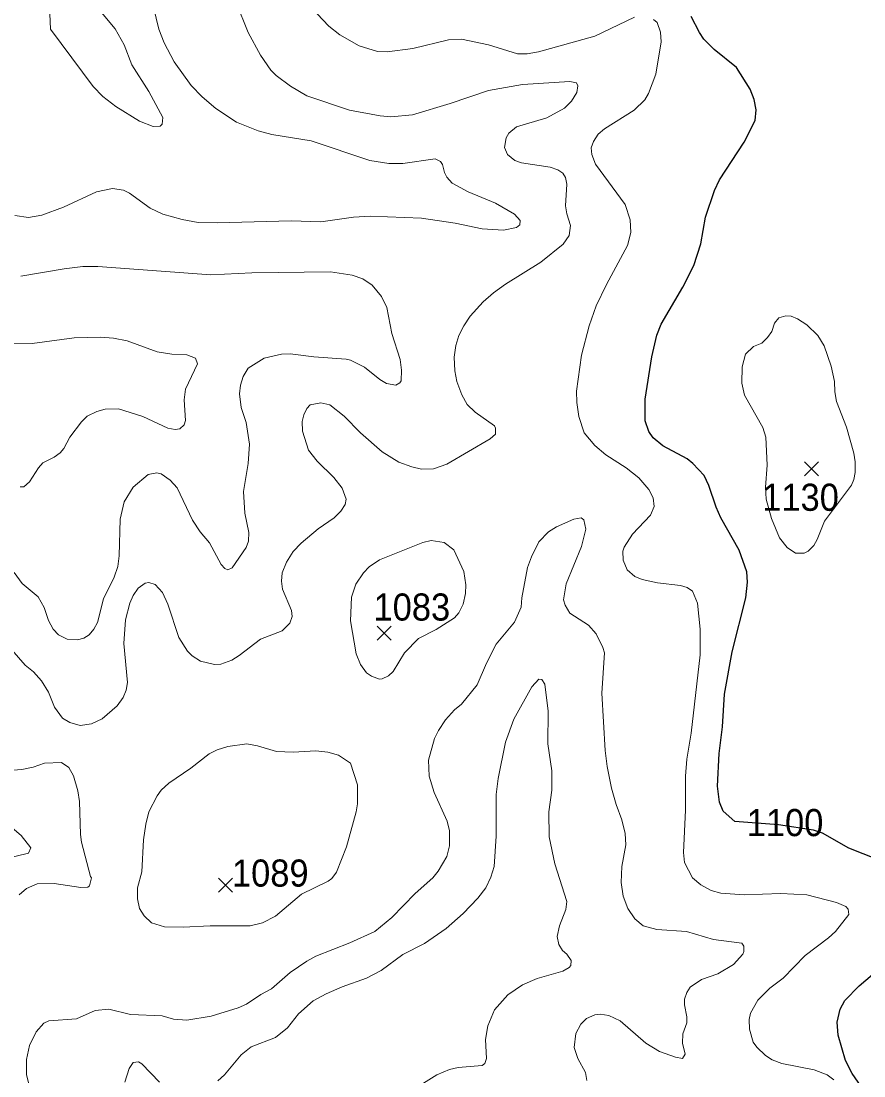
# Model space of a CAD drawing. Extents: x 265 to 291.4, y 7731.5 to 7759.6.
# Drawn here: x 278.229 to 280.715, y 7740.103 to 7743.215 of the extents above; entities that cross this region are included whole.
import ezdxf
from ezdxf.enums import TextEntityAlignment as Align

# ---------------------------------------------------------------- set-up
doc = ezdxf.new("R2010")
doc.units = 0
doc.header["$LTSCALE"] = 0.032
for name, color, linetype, lineweight in [('1', 7, 'Continuous', 25), ('2', 7, 'Continuous', 13), ('21', 7, 'Continuous', 25), ('61', 7, 'Continuous', 13)]:
    doc.layers.add(name, color=color, linetype=linetype, lineweight=lineweight)

msp = doc.modelspace()

# ---------------------------------------------------------------- linework, layer by layer
at = {"layer": '1'}
for points in [[(280.0695, 7742.0994), (280.0894, 7742.225), (280.1037, 7742.2887), (280.1165, 7742.3205), (280.1809, 7742.4303), (280.2127, 7742.4939), (280.2334, 7742.5576), (280.2477, 7742.6371), (280.274, 7742.7151), (280.2883, 7742.7469), (280.3615, 7742.8583), (280.3941, 7742.9219), (280.3973, 7742.9537), (280.3909, 7742.9839), (280.379, 7743.0142), (280.3384, 7743.0778), (280.2732, 7743.1311), (280.243, 7743.1613), (280.2294, 7743.1812), (280.2048, 7743.2289)], [(280.2103, 7741.91), (280.1929, 7741.9235), (280.1213, 7741.9617), (280.0926, 7741.9856), (280.0807, 7742.0039), (280.0695, 7742.0357), (280.0695, 7742.0994)], [(280.7974, 7740.7247), (280.6701, 7740.7756), (280.593, 7740.8194), (280.5655, 7740.8287), (280.4625, 7740.844), (280.3344, 7740.8544), (280.2994, 7740.8846), (280.2891, 7740.9109), (280.2827, 7740.9586), (280.2875, 7741.0541), (280.2978, 7741.1336), (280.3034, 7741.2291), (280.3257, 7741.3548), (280.3663, 7741.5139), (280.3718, 7741.56), (280.3694, 7741.5903), (280.3464, 7741.6539), (280.2931, 7741.7493), (280.2787, 7741.7812), (280.2573, 7741.8448), (280.2437, 7741.875), (280.2103, 7741.91)], [(280.7258, 7740.0438), (280.6797, 7740.1107), (280.6606, 7740.1488), (280.6383, 7740.2236), (280.6359, 7740.2618), (280.6447, 7740.3), (280.6582, 7740.3254), (280.7003, 7740.3692), (280.8117, 7740.4638)]]:
    msp.add_lwpolyline(points, dxfattribs=at)
at = {"layer": '2'}
for points in [[(278.5939, 7743.3626), (278.6345, 7743.1908), (278.6504, 7743.151), (278.6806, 7743.0945), (278.7307, 7743.0253), (278.7626, 7742.9919), (278.8031, 7742.9569), (278.8644, 7742.9171), (278.928, 7742.8909), (278.9678, 7742.8805), (279.084, 7742.8614), (279.2574, 7742.8042), (279.3131, 7742.7954), (279.3544, 7742.7946), (279.4499, 7742.8089), (279.4658, 7742.801), (279.4713, 7742.7922), (279.4777, 7742.7684), (279.4849, 7742.7548), (279.5, 7742.7373), (279.5469, 7742.7111), (279.6281, 7742.6777), (279.6845, 7742.6451), (279.7012, 7742.6268), (279.6996, 7742.614), (279.6901, 7742.6061), (279.6519, 7742.5981), (279.5883, 7742.6021), (279.5087, 7742.6188), (279.4101, 7742.6339), (279.259, 7742.6395), (279.2096, 7742.6363), (279.1126, 7742.6228), (279.0251, 7742.626), (278.8071, 7742.6196), (278.7514, 7742.6212), (278.7037, 7742.6299)], [(278.3131, 7743.2369), (278.3155, 7743.1915), (278.4412, 7743.0221), (278.4698, 7742.9927), (278.508, 7742.9632), (278.578, 7742.9195), (278.6178, 7742.9044), (278.6385, 7742.9052), (278.6448, 7742.9107), (278.6464, 7742.9306), (278.6051, 7743.0078), (278.5549, 7743.0858), (278.5327, 7743.1446), (278.5064, 7743.1924), (278.4515, 7743.2584)], [(278.9654, 7743.0706), (278.9344, 7743.1144), (278.8986, 7743.1812), (278.862, 7743.2719)], [(279.1022, 7743.2361), (279.1364, 7743.2003), (279.1691, 7743.174), (279.2255, 7743.1422), (279.2796, 7743.1255), (279.3083, 7743.1239), (279.3846, 7743.1343), (279.4896, 7743.1597), (279.5278, 7743.1621), (279.6074, 7743.1454), (279.6933, 7743.1184), (279.7219, 7743.1184), (279.7553, 7743.1247), (279.9208, 7743.1701), (280.0377, 7743.2265)], [(280.0942, 7743.2202), (280.1053, 7743.2106), (280.1149, 7743.1828), (280.1165, 7743.1542), (280.1014, 7743.0587), (280.0791, 7743.0014), (280.068, 7742.9823), (280.0369, 7742.9521), (279.9494, 7742.8972), (279.9311, 7742.8813), (279.9168, 7742.8598), (279.9104, 7742.8408), (279.912, 7742.8217), (279.9232, 7742.793), (280.0107, 7742.6737), (280.025, 7742.6292), (280.0274, 7742.591), (280.017, 7742.5528), (279.955, 7742.4382), (279.9248, 7742.3746), (279.9041, 7742.3157), (279.8818, 7742.2298), (279.8667, 7742.1232), (279.8675, 7742.0898), (279.8739, 7742.0485), (279.8898, 7742.0007), (279.9208, 7741.9633), (279.9534, 7741.9355), (280.0131, 7741.8973), (280.0505, 7741.8679), (280.0799, 7741.8329)], [(279.3194, 7742.933), (279.2876, 7742.9354), (279.1969, 7742.9521), (279.0712, 7742.9943), (279.0235, 7743.0229), (278.9813, 7743.0547), (278.9654, 7743.0706)], [(278.5947, 7741.5568), (278.6056, 7741.5588), (278.6241, 7741.5528), (278.6456, 7741.529), (278.6615, 7741.4948), (278.6941, 7741.3962), (278.7196, 7741.3564), (278.7331, 7741.3429), (278.7578, 7741.3269), (278.7992, 7741.3166), (278.8183, 7741.3182), (278.8501, 7741.3301), (278.8724, 7741.3436), (278.9344, 7741.3922), (278.9988, 7741.416), (279.0211, 7741.4391), (279.0283, 7741.4582), (279.0267, 7741.4765), (278.9996, 7741.5393), (278.9964, 7741.5632), (278.9988, 7741.5871), (279.0115, 7741.6189), (279.0314, 7741.6507), (279.0545, 7741.6746), (279.1046, 7741.7175), (279.1524, 7741.7501), (279.1714, 7741.7692), (279.1842, 7741.7891), (279.1874, 7741.805), (279.1754, 7741.8369), (279.1508, 7741.8687), (279.1022, 7741.9172), (279.0768, 7741.949), (279.0585, 7742.0055), (279.0577, 7742.0341), (279.0625, 7742.0532), (279.072, 7742.0723), (279.0816, 7742.0835), (279.1126, 7742.089), (279.1396, 7742.0826), (279.1818, 7742.05), (279.2295, 7742.0007), (279.294, 7741.9442), (279.3433, 7741.914), (279.3815, 7741.8997), (279.4101, 7741.8933), (279.4451, 7741.8941), (279.4849, 7741.9076), (279.6121, 7741.9824), (279.6281, 7741.9967), (279.6281, 7742.0142), (279.6249, 7742.0206), (279.5676, 7742.0612), (279.5445, 7742.0842), (279.5286, 7742.1121), (279.5143, 7742.1519), (279.5079, 7742.1837), (279.5063, 7742.2235), (279.5111, 7742.2585), (279.5199, 7742.2871), (279.5342, 7742.3157), (279.5533, 7742.3444), (279.5915, 7742.3865), (279.6217, 7742.4136), (279.6575, 7742.439), (279.7617, 7742.5034), (279.8277, 7742.5568), (279.8452, 7742.583), (279.8492, 7742.6117), (279.8381, 7742.6467), (279.8341, 7742.6705), (279.8389, 7742.7342), (279.8349, 7742.754), (279.8269, 7742.766), (279.8118, 7742.7763), (279.7888, 7742.7843), (279.7044, 7742.797), (279.6853, 7742.8042), (279.6631, 7742.8217), (279.6543, 7742.8423), (279.6591, 7742.871), (279.667, 7742.8845), (279.6901, 7742.9028), (279.7792, 7742.9298), (279.8317, 7742.9585), (279.8524, 7742.9792), (279.8675, 7743.0046), (279.8707, 7743.0245), (279.8667, 7743.0325), (279.8476, 7743.0372), (279.7076, 7743.0277), (279.6074, 7743.0102), (279.4944, 7742.972), (279.3831, 7742.9386), (279.3194, 7742.933)], [(278.7037, 7742.6299), (278.6464, 7742.6458), (278.6098, 7742.6633), (278.5486, 7742.7079), (278.5303, 7742.7158), (278.4985, 7742.7214), (278.4507, 7742.7111)], [(278.4507, 7742.7111), (278.3537, 7742.6665), (278.2901, 7742.6427), (278.2503, 7742.6355), (278.2105, 7742.6411)], [(278.228, 7742.4629), (278.3553, 7742.4844), (278.411, 7742.4907), (278.4555, 7742.4907), (278.788, 7742.4669), (278.9089, 7742.4724), (279.1412, 7742.4756), (279.2049, 7742.4653), (279.2367, 7742.4549), (279.2645, 7742.4358), (279.2916, 7742.4024), (279.3075, 7742.3698), (279.3226, 7742.2935), (279.3472, 7742.2171), (279.3512, 7742.1853), (279.3496, 7742.1542), (279.3457, 7742.1479), (279.3345, 7742.1415), (279.3067, 7742.1463), (279.2868, 7742.1574), (279.2415, 7742.194), (279.2001, 7742.2147), (279.1874, 7742.2179), (279.0919, 7742.2242), (279.0219, 7742.233), (278.9964, 7742.2322), (278.9455, 7742.2203), (278.8986, 7742.1908), (278.8835, 7742.167), (278.8755, 7742.1407), (278.8731, 7742.1153), (278.8779, 7742.0755)], [(278.2256, 7741.8416), (278.2367, 7741.8416), (278.2535, 7741.8559), (278.2805, 7741.8973), (278.2932, 7741.9116), (278.3267, 7741.9283), (278.3442, 7741.9418), (278.3545, 7741.9546), (278.3728, 7741.988), (278.407, 7742.0333), (278.4237, 7742.0492), (278.4523, 7742.0636), (278.4762, 7742.0707), (278.516, 7742.0715), (278.5876, 7742.0484), (278.6615, 7742.0142), (278.683, 7742.0102), (278.6973, 7742.0118), (278.7093, 7742.0238), (278.714, 7742.0373), (278.7101, 7742.0978), (278.714, 7742.1296), (278.749, 7742.2035), (278.7435, 7742.2211), (278.718, 7742.2306), (278.6735, 7742.2322), (278.6305, 7742.2394), (278.5414, 7742.272), (278.5017, 7742.2799), (278.4619, 7742.2823), (278.3855, 7742.2807), (278.2614, 7742.264), (278.2057, 7742.2632)], [(278.8779, 7742.0755), (278.8922, 7742.031), (278.9026, 7741.9673), (278.8986, 7741.91), (278.8843, 7741.8273), (278.889, 7741.7637), (278.9002, 7741.7064)], [(278.9002, 7741.7064), (278.8994, 7741.6809), (278.893, 7741.6618), (278.8509, 7741.6022), (278.8389, 7741.5966), (278.8294, 7741.5998), (278.819, 7741.6125), (278.7848, 7741.6762), (278.757, 7741.7088), (278.7347, 7741.743), (278.6886, 7741.8384), (278.6687, 7741.8607), (278.6417, 7741.879), (278.6289, 7741.8822), (278.6035, 7741.8774), (278.5589, 7741.84), (278.5327, 7741.7971), (278.5207, 7741.7462), (278.5176, 7741.638), (278.5136, 7741.6062), (278.5032, 7741.5743), (278.4722, 7741.5107), (278.4539, 7741.4407), (278.4436, 7741.4216), (278.4293, 7741.4041), (278.4142, 7741.3945), (278.3951, 7741.3898), (278.3648, 7741.3914), (278.3394, 7741.4041), (278.3235, 7741.4216), (278.3099, 7741.4471), (278.2972, 7741.4852), (278.2789, 7741.5171), (278.232, 7741.556), (278.2081, 7741.5887)], [(280.0799, 7741.8329), (280.0926, 7741.8082), (280.0958, 7741.7835), (280.0855, 7741.7573), (280.0322, 7741.7016), (280.0075, 7741.6634), (280.0035, 7741.6515)], [(280.0123, 7740.7852), (280.0107, 7740.8186), (280.0011, 7740.8584), (279.9836, 7740.9045), (279.9701, 7740.9523), (279.9574, 7741.0159), (279.9518, 7741.0636), (279.9415, 7741.2323), (279.9494, 7741.3516), (279.9446, 7741.3675), (279.9248, 7741.4073), (279.9025, 7741.4327), (279.8476, 7741.4685), (279.8333, 7741.4916), (279.8285, 7741.5075), (279.8365, 7741.5553), (279.8818, 7741.665), (279.8945, 7741.7159), (279.889, 7741.7438), (279.881, 7741.7493), (279.8587, 7741.7461), (279.8078, 7741.7231), (279.784, 7741.708), (279.7561, 7741.6785), (279.7338, 7741.6348), (279.7227, 7741.603), (279.7052, 7741.5139), (279.7036, 7741.486), (279.6845, 7741.4423), (279.6304, 7741.3771), (279.6018, 7741.3214), (279.574, 7741.2569), (279.5278, 7741.2005), (279.5071, 7741.183), (279.4809, 7741.1535), (279.4594, 7741.1225), (279.4483, 7741.0986), (279.43, 7741.035), (279.4324, 7740.9873), (279.4467, 7740.9395), (279.4857, 7740.8552), (279.492, 7740.8266), (279.492, 7740.782), (279.4841, 7740.7502), (279.4586, 7740.7073), (279.4435, 7740.6882), (279.391, 7740.642), (279.3226, 7740.5704), (279.2725, 7740.5299), (279.1985, 7740.4956), (279.0983, 7740.4567), (279.0712, 7740.4424), (279.0227, 7740.4089), (278.967, 7740.3604), (278.936, 7740.3437), (278.8938, 7740.3151), (278.8692, 7740.3039), (278.7896, 7740.2801), (278.718, 7740.2681), (278.6783, 7740.2705), (278.6448, 7740.2809), (278.551, 7740.2841), (278.4873, 7740.3), (278.4476, 7740.296), (278.3919, 7740.2721), (278.3107, 7740.2658), (278.2956, 7740.2594), (278.2733, 7740.2339), (278.2534, 7740.1934), (278.2447, 7740.152), (278.2447, 7740.1075), (278.2606, 7740.0438)], [(280.0035, 7741.6515), (280.0043, 7741.6253), (280.0162, 7741.5966), (280.0393, 7741.5767), (280.0608, 7741.568), (280.1054, 7741.5584), (280.1738, 7741.5505), (280.1929, 7741.5441), (280.2088, 7741.5338), (280.2239, 7741.498), (280.2318, 7741.4216), (280.2318, 7741.3452), (280.2048, 7741.1146), (280.192, 7741.0382), (280.1881, 7740.9873), (280.1881, 7740.887), (280.1825, 7740.7629), (280.1857, 7740.7327), (280.2087, 7740.6882), (280.2334, 7740.6667), (280.2645, 7740.6508), (280.2931, 7740.6428), (280.3615, 7740.6372), (280.4697, 7740.642), (280.5461, 7740.6373), (280.6336, 7740.615), (280.6614, 7740.6031), (280.6685, 7740.5951), (280.6701, 7740.5792), (280.6312, 7740.5299), (280.6105, 7740.5108), (280.5413, 7740.4591), (280.4768, 7740.3914), (280.4371, 7740.362), (280.4013, 7740.327), (280.3798, 7740.2888), (280.3766, 7740.2697), (280.3774, 7740.2411), (280.3877, 7740.2029), (280.3989, 7740.1878), (280.4243, 7740.1639), (280.4442, 7740.1512), (280.4729, 7740.1401), (280.5683, 7740.1218), (280.6065, 7740.1067), (280.6256, 7740.0915)], [(278.189, 7741.3755), (278.2407, 7741.315), (278.2654, 7741.2951), (278.2884, 7741.2689), (278.3091, 7741.2355), (278.3274, 7741.1909), (278.3513, 7741.1591), (278.372, 7741.1456), (278.403, 7741.1368), (278.4364, 7741.1416), (278.4682, 7741.1567), (278.512, 7741.1949), (278.5295, 7741.2196), (278.539, 7741.2418), (278.5422, 7741.2641), (278.5319, 7741.3787), (278.5366, 7741.4487), (278.5494, 7741.498), (278.5589, 7741.5202), (278.574, 7741.5425), (278.5947, 7741.5568)], [(278.8087, 7740.0892), (278.8286, 7740.1067), (278.8779, 7740.1655), (278.9074, 7740.1894), (278.9789, 7740.2164), (279.0147, 7740.2451), (279.0466, 7740.2864), (279.0903, 7740.3246), (279.1285, 7740.3453), (279.1762, 7740.366), (279.2478, 7740.3914), (279.2908, 7740.4145), (279.3544, 7740.4614), (279.4181, 7740.4941), (279.4825, 7740.5386), (279.5326, 7740.5824), (279.5756, 7740.6277), (279.5994, 7740.6579), (279.6145, 7740.6898), (279.6241, 7740.7216), (279.6304, 7740.8107), (279.6304, 7740.9332), (279.636, 7740.9809), (279.6575, 7741.0875), (279.6821, 7741.1559), (279.7354, 7741.2514), (279.7561, 7741.2736)], [(279.7561, 7741.2736), (279.7649, 7741.2728), (279.7736, 7741.2593), (279.7832, 7741.1798), (279.7824, 7741.0827), (279.7943, 7741.0032), (279.7943, 7740.9459)], [(278.2232, 7740.6373), (278.2447, 7740.6563), (278.2757, 7740.6699), (278.3267, 7740.6715), (278.4046, 7740.6595), (278.4253, 7740.6603), (278.4309, 7740.6643), (278.4364, 7740.6874), (278.4332, 7740.6913), (278.407, 7740.7932), (278.4038, 7740.8154), (278.4006, 7740.9125), (278.3958, 7740.9443), (278.3831, 7740.9889), (278.3696, 7741.0135), (278.3481, 7741.0278), (278.298, 7741.0262), (278.2646, 7741.0143), (278.2312, 7741.0071), (278.1373, 7741)], [(279.7943, 7740.9459), (279.7856, 7740.8823), (279.7864, 7740.8091), (279.8031, 7740.7295), (279.8389, 7740.6182), (279.8357, 7740.5943), (279.8166, 7740.5466), (279.8102, 7740.5148), (279.815, 7740.4909), (279.8253, 7740.4734), (279.8381, 7740.463), (279.8508, 7740.4439), (279.85, 7740.4296), (279.8452, 7740.4233), (279.8269, 7740.4129), (279.7506, 7740.3907), (279.7076, 7740.3724), (279.6639, 7740.3429), (279.6249, 7740.2984), (279.605, 7740.2507), (279.5986, 7740.2109), (279.6018, 7740.1552), (279.597, 7740.1401), (279.5883, 7740.1337), (279.5183, 7740.1281), (279.4928, 7740.1226), (279.4546, 7740.1067), (279.3998, 7740.0724)], [(278.1819, 7740.8528), (278.2288, 7740.8131), (278.2574, 7740.7765), (278.2503, 7740.7606), (278.1819, 7740.7438)], [(280.064, 7740.5458), (280.0393, 7740.5665), (280.0186, 7740.5975), (280.0043, 7740.6341), (279.9988, 7740.6739), (280.0011, 7740.7216), (280.0123, 7740.7852)], [(279.8977, 7740.09), (279.8938, 7740.113), (279.8707, 7740.1552), (279.8603, 7740.187), (279.8651, 7740.2284), (279.8794, 7740.2562), (279.8961, 7740.2729), (279.9208, 7740.2833), (279.9367, 7740.2856), (279.9622, 7740.2817), (279.9956, 7740.2658), (280.0711, 7740.2005), (280.1117, 7740.1751), (280.1594, 7740.1584), (280.1793, 7740.1552), (280.1873, 7740.1679), (280.1793, 7740.1997), (280.1801, 7740.2276), (280.192, 7740.2602), (280.192, 7740.2777), (280.1857, 7740.3127), (280.1857, 7740.3302), (280.192, 7740.3493), (280.2024, 7740.3652), (280.2358, 7740.3883), (280.2835, 7740.405), (280.3297, 7740.432), (280.3575, 7740.4623), (280.3607, 7740.4702), (280.3607, 7740.4861), (280.3543, 7740.4949), (280.2708, 7740.506), (280.1913, 7740.5299), (280.1038, 7740.5354), (280.064, 7740.5458)], [(278.5343, 7740.0852), (278.547, 7740.125), (278.5589, 7740.1425), (278.5748, 7740.1448), (278.5844, 7740.1393), (278.6369, 7740.0852)]]:
    msp.add_lwpolyline(points, dxfattribs=at)
for points in [[(280.3623, 7742.1113), (280.3543, 7742.1471), (280.3559, 7742.1948), (280.3655, 7742.2322), (280.3893, 7742.2553), (280.414, 7742.2648), (280.4307, 7742.2815), (280.4434, 7742.2998), (280.4514, 7742.3237), (280.4641, 7742.3396), (280.484, 7742.3459), (280.4999, 7742.3444), (280.519, 7742.3364), (280.5461, 7742.3189), (280.5787, 7742.2879), (280.5977, 7742.2569), (280.6184, 7742.1972), (280.628, 7742.1519), (280.6288, 7742.1216), (280.6338, 7742.093), (280.663, 7742.0174), (280.6852, 7741.9403), (280.6892, 7741.9148), (280.6892, 7741.883), (280.6852, 7741.8623), (280.6781, 7741.8464), (280.5985, 7741.7398), (280.5771, 7741.6857), (280.5667, 7741.6682), (280.55, 7741.6515), (280.5381, 7741.6451), (280.5126, 7741.6451), (280.488, 7741.6626), (280.4657, 7741.6905), (280.4418, 7741.7478), (280.4259, 7741.805), (280.4243, 7741.84), (280.4291, 7741.9053), (280.4251, 7741.988), (280.4164, 7742.0166)], [(279.5409, 7741.5525), (279.5342, 7741.5918), (279.5055, 7741.6555), (279.4769, 7741.6769), (279.4387, 7741.6825), (279.4133, 7741.6769), (279.286, 7741.626), (279.2558, 7741.6054), (279.2383, 7741.5879), (279.216, 7741.5537), (279.2033, 7741.5155), (279.2001, 7741.4455), (279.2168, 7741.3484), (279.2295, 7741.3166), (279.2478, 7741.2927), (279.2621, 7741.2824), (279.286, 7741.2736), (279.294, 7741.2744), (279.3123, 7741.284), (279.3266, 7741.2959), (279.36, 7741.3516), (279.4013, 7741.3938), (279.4531, 7741.42), (279.5071, 7741.455), (279.5199, 7741.4693), (279.5326, 7741.4948), (279.5398, 7741.5266)], [(278.5899, 7740.7995), (278.5963, 7740.8457), (278.6059, 7740.8823), (278.6297, 7740.93), (278.6416, 7740.9459), (278.6647, 7740.9674), (278.7292, 7741.0111), (278.7833, 7741.0533), (278.8071, 7741.0652), (278.8389, 7741.0756), (278.8946, 7741.0827), (278.9264, 7741.0772), (278.9821, 7741.0604), (279.0315, 7741.0589), (279.0983, 7741.062), (279.1333, 7741.0589), (279.1651, 7741.0493), (279.2001, 7741.0262), (279.2208, 7740.9618), (279.2208, 7740.9061), (279.2168, 7740.8823), (279.1881, 7740.7789), (279.1595, 7740.7041), (279.1452, 7740.6858), (279.1349, 7740.6778), (279.0553, 7740.6396), (278.9789, 7740.5744), (278.9408, 7740.5553), (278.9042, 7740.5458), (278.7864, 7740.5458), (278.7069, 7740.5418), (278.6512, 7740.5434), (278.613, 7740.5553), (278.5915, 7740.576), (278.578, 7740.5975), (278.5716, 7740.6261), (278.5724, 7740.6579), (278.5844, 7740.7057)]]:
    msp.add_lwpolyline(points, close=True, dxfattribs=at)
at = {"layer": '21'}
for p, q in [((280.5394, 7741.915), (280.5806, 7741.8738)), ((280.5806, 7741.915), (280.5394, 7741.8738)), ((279.2791, 7741.4301), (279.3203, 7741.3889)), ((279.3203, 7741.4301), (279.2791, 7741.3889)), ((278.8108, 7740.6868), (278.852, 7740.6456)), ((278.852, 7740.6868), (278.8108, 7740.6456))]:
    msp.add_line(p, q, dxfattribs=at)

# ---------------------------------------------------------------- texts
at = {"layer": '61', "width": 0.95}
for s, p in [('1130', (280.5278, 7741.7704)), ('1083', (279.3813, 7741.4466)), ('1100', (280.482, 7740.8107)), ('1089', (278.9637, 7740.6618))]:
    msp.add_text(s, height=0.08, dxfattribs=at).set_placement(p, align=Align.CENTER)

doc.saveas('drawing.dxf')
